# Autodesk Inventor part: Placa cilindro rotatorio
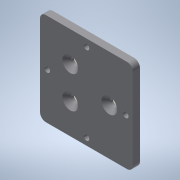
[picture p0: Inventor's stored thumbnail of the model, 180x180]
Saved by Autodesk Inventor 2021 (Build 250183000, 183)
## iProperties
Created: 2021-02
Part Number: Placa cilindro rotatorio
Material: Genérico
Document SubType Name: Modeling
Designer: ATOUZA
Density: 1 g/cm^3
Appearance: Valor por defecto
Author: ATOUZA
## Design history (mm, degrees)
node "Plano de trabajo1"
sketch "Boceto1"
  geometry: L1 (55, 32.5)-(-10, 32.5); L2 (-10, 32.5)-(-10, -32.5); L3 (-10, -32.5)-(55, -32.5); L4 (55, -32.5)-(55, 32.5); L5 (55, 32.5)-(-10, -32.5); L6 (-10, 32.5)-(55, -32.5); L7 (22.5, 22.5)-(22.5, 32.5); L8 (22.5, 16)-(22.5, -16); C1 r 2.5 at (33.814, 11.314) reference; C2 r 2.5 at (22.5, 16) reference; C3 r 2.5 at (11.186, 11.314) reference; C4 r 2.5 at (6.5, 0) reference; C5 r 2.5 at (11.186, -11.314) reference; C6 r 2.5 at (22.5, -16) reference; C7 r 2.5 at (33.814, -11.314) reference; C8 r 2.5 at (38.5, 0) reference; C9 r 2.5 at (38.5, 0); C10 r 2.5 at (11.186, 11.314); C11 r 2.5 at (11.186, -11.314); C12 r 2 at (22.5, 27.5); C13 r 2 at (-5, 0); C14 r 2 at (22.5, -27.5); C15 r 2 at (50, 0); A1 r 22.5 centre (22.5, 0) between (0, 0) and (22.5, 22.5) reference
  constraints: 16 end point, 7 centre point, 4 midpoint, 3 coincident, 3 concentric, 2 parallel, 1 horizontal, 1 perpendicular, 1 point on circle, 1 vertical, 9 other
  dimensions: "d0" = 65 distance of L3.end L2.end; "d1" = 65 distance of L2.end L1.end; "d26" = 4 diameter of C12; "d30" = 360 deg dimension on A1.centre C12.centre (derived)
extrude "Extrusión1" new body sketch "Boceto1" distance "d2" = 5; taper "d3" = 0 deg
fillet "Empalme1" dims "d4" = 4
sketch "Boceto4"
  geometry: C1 r 2.5 at (11.186, 11.314) reference; C2 r 2.5 at (11.186, -11.314) reference; C3 r 2.5 at (38.5, 0) reference; 4 further points
  constraints: 3 coincident
hole "Agujero3" sketch "Boceto4" at (11.186, 11.314), (11.186, -11.314), (38.5, 0) diameter "d19" = 5; stored, may be unused: countersink angle "d23" = 90 deg, drill point angle "d25" = 118 deg; dims "d20" = 6, "d21" = 11, "d22" = 2, "d24" = 8
sketch "Boceto5"
  geometry: L1 (55, -28.5)-(55, 28.5) reference; L2 (51, 32.5)-(-6, 32.5) reference; L3 (-10, 28.5)-(-10, -28.5) reference; L4 (-6, -32.5)-(51, -32.5) reference; C1 r 5.5 at (11.186, -11.314) reference; C2 r 5.5 at (11.186, 11.314) reference; C3 r 5.5 at (38.5, 0) reference; C4 r 2 at (22.5, 27.5) reference; C5 r 2 at (-5, 0) reference; C6 r 2 at (22.5, -27.5) reference; C7 r 2 at (50, 0) reference; A1 r 4 centre (51, -28.5) between (51, -32.5) and (55, -28.5) reference; A2 r 4 centre (51, 28.5) between (55, 28.5) and (51, 32.5) reference; A3 r 4 centre (-6, 28.5) between (-6, 32.5) and (-10, 28.5) reference; A4 r 4 centre (-6, -28.5) between (-10, -28.5) and (-6, -32.5) reference; 1 further point
  node "Contorno proyectado1"
node "Sólido1"
node "Referencia1"
node "Referencia2"
node "Referencia3"
node "Referencia4"
node "Referencia5"
node "Referencia6"
node "Referencia7"
node "Referencia8"
node "Referencia9"
